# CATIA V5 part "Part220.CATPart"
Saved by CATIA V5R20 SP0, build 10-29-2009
Part number: DFA 168700-3
Revision: ANY
Definition: UNKNOWN
Nomenclature: DFA 168700-3
Source: Unknown
Bounding box of the stored display mesh (mm): x -3 to 3, y 0 to 4.95, z -3.464 to 3.464
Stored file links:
  C:\Users\Utente\Desktop\IO LAVORO\3D X SITO CF\CUMSA\3D files FA\FA 200710-21\Part220.CATPart

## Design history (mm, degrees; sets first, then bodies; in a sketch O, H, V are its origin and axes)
Body1 "Cortar-Extruir3" (main body)
  Solid1: solid without history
